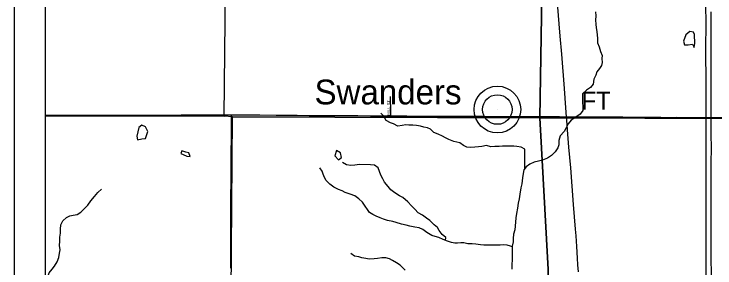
# Model space of a CAD drawing. Extents: x 0 to 1391, y -24 to 440.
# Drawn here: x 490 to 534.79, y 365.71 to 381.91 of the extents above; entities that cross this region are included whole.
import ezdxf

# ---------------------------------------------------------------- set-up
doc = ezdxf.new("R2010")
doc.units = 0
for name, color, linetype in [('GM_X_County_Road', 7, 'Continuous'), ('GM_X_County_Road_Text', 7, 'Continuous'), ('GM_X_Interstate_Route', 7, 'Continuous'), ('GM_X_Minor_Lake', 7, 'Continuous'), ('GM_X_Minor_River', 7, 'Continuous'), ('GM_X_Section', 7, 'Continuous'), ('GM_X_Township', 7, 'Continuous'), ('GM_X_Township_Road', 7, 'Continuous'), ('GM_X_Township_Subdivision', 7, 'Continuous'), ('GM_X_Township_Subdivision_Text', 7, 'Continuous'), ('GM_X_Unincorporated', 7, 'Continuous'), ('GM_X_Unincorporated_Location', 7, 'Continuous'), ('GM_X_Unincorporated_Text', 7, 'Continuous'), ('SH_Data', 7, 'Continuous')]:
    doc.layers.add(name, color=color, linetype=linetype)

msp = doc.modelspace()

# ---------------------------------------------------------------- linework, layer by layer
at = {"layer": 'GM_X_County_Road'}
for points in [[(525.306, 375.36), (525.265, 375.917), (525.169, 377.156), (524.994, 379.348), (524.898, 380.487), (524.731, 382.594), (524.682, 383.226), (524.546, 384.923), (524.496, 385.53), (524.433, 386.31), (524.345, 387.425), (524.25, 388.552), (524.156, 389.753), (524.084, 390.608), (524.005, 391.636), (523.947, 392.283)], [(492, 375.458), (492.953, 375.453), (494.159, 375.455), (495.712, 375.459), (496.11, 375.458), (496.47, 375.458), (497.079, 375.466), (497.899, 375.462), (498.67, 375.462), (499.341, 375.463), (500.086, 375.462), (500.671, 375.471), (501.292, 375.476), (501.677, 375.479), (502.013, 375.479), (503.082, 375.481), (503.84, 375.48), (503.894, 375.481)], [(503.894, 375.481), (504.386, 375.484), (504.809, 375.482), (505.256, 375.477), (505.716, 375.472), (506.747, 375.458), (507.505, 375.452), (508.089, 375.448), (508.86, 375.441), (509.344, 375.439), (509.73, 375.435), (509.991, 375.433), (510.425, 375.43), (511.022, 375.429), (511.382, 375.429), (511.978, 375.426), (512.773, 375.417), (513.158, 375.409), (514.073, 375.406)], [(514.073, 375.406), (514.897, 375.406), (515.092, 375.405)], [(515.092, 375.405), (515.431, 375.403), (515.854, 375.402), (516.587, 375.402), (517.271, 375.402), (517.544, 375.398), (517.705, 375.395), (518.103, 375.396), (518.712, 375.389), (518.823, 375.387), (519.146, 375.384), (519.369, 375.386), (520.014, 375.385), (520.374, 375.382), (520.685, 375.378), (521.231, 375.372), (521.827, 375.371), (523.406, 375.371), (524.388, 375.368), (524.848, 375.365), (525.306, 375.36)], [(526.06, 365.472), (526.036, 365.906), (526.013, 366.34), (525.966, 367.072), (525.916, 367.766), (525.882, 368.187), (525.758, 369.76), (525.569, 372.089), (525.461, 373.426), (525.373, 374.529), (525.323, 375.136), (525.306, 375.36)], [(525.306, 375.36), (525.324, 375.359), (525.581, 375.358), (525.991, 375.357), (526.513, 375.355), (527.172, 375.35), (527.83, 375.347), (528.911, 375.341), (529.707, 375.336), (530.204, 375.331), (530.751, 375.329), (531.024, 375.332), (531.323, 375.324), (531.807, 375.319), (532.353, 375.32), (533.346, 375.317), (533.794, 375.315), (534.218, 375.312), (534.553, 375.312), (535.968, 375.307)]]:
    msp.add_lwpolyline(points, dxfattribs=at)
at = {"layer": 'GM_X_Interstate_Route'}
for points in [[(534.218, 365.027), (534.22, 365.922), (534.222, 366.63), (534.218, 368.333), (534.222, 369.501), (534.218, 370.408), (534.22, 371.601), (534.217, 372.546), (534.217, 374.36), (534.218, 375.312), (534.216, 376.386), (534.218, 377.815), (534.214, 379.282), (534.213, 379.928), (534.216, 381.071), (534.213, 382.737)], [(534.557, 365.164), (534.554, 366.494), (534.551, 367.078), (534.552, 368.768), (534.554, 369.265), (534.555, 369.738), (534.555, 370.086), (534.552, 370.694), (534.552, 371.266), (534.553, 371.962), (534.554, 372.385), (534.555, 372.496), (534.555, 372.77), (534.556, 372.993), (534.556, 373.043), (534.556, 373.242), (534.555, 374.36), (534.553, 375.312), (534.551, 376.808), (534.551, 377.505), (534.55, 378.25), (534.551, 378.511), (534.547, 379.791), (534.545, 380.239), (534.547, 380.674), (534.551, 382.041)]]:
    msp.add_lwpolyline(points, dxfattribs=at)
at = {"layer": 'GM_X_Minor_Lake'}
for p, q in [((500.722, 373.183), (500.652, 373.016)), ((500.652, 373.016), (500.817, 372.946)), ((501.248, 372.832), (501.176, 373.045)), ((510.931, 372.75), (510.868, 373.062))]:
    msp.add_line(p, q, dxfattribs=at)
for points in [[(533.472, 380.598), (533.423, 380.76), (533.18, 380.795), (532.925, 380.581), (532.787, 380.178)], [(532.787, 380.178), (532.846, 379.946), (533.081, 379.949), (533.356, 379.981), (533.451, 379.774), (533.509, 380.038), (533.472, 380.598)], [(498.547, 374.419), (498.4, 374.707), (498.159, 374.81), (497.966, 374.663), (497.844, 374.121)], [(497.844, 374.121), (497.899, 373.884), (498.159, 373.954), (498.402, 373.972), (498.547, 374.419)], [(501.176, 373.045), (500.979, 373.095), (500.722, 373.183)], [(510.868, 373.062), (510.612, 373.211), (510.495, 372.862)], [(500.817, 372.946), (501.051, 372.851), (501.248, 372.832)], [(510.495, 372.862), (510.731, 372.618), (510.931, 372.75)]]:
    msp.add_lwpolyline(points, dxfattribs=at)
at = {"layer": 'GM_X_Minor_River'}
for points in [[(527.162, 382.048), (527.167, 381.798), (527.155, 381.518), (527.167, 381.268), (527.202, 381.017), (527.237, 380.789), (527.257, 380.554), (527.285, 380.364), (527.281, 380.069), (527.392, 379.809), (527.479, 379.528), (527.575, 379.268), (527.557, 379.072), (527.577, 378.821), (527.544, 378.625), (527.42, 378.43), (527.25, 378.221), (527.171, 378.017), (527.038, 377.747), (527.004, 377.444), (526.833, 377.212), (526.58, 377.057), (526.334, 376.818), (526.33, 376.546), (526.319, 376.258), (526.354, 376.015), (526.336, 375.765), (526.18, 375.525), (525.889, 375.34), (525.605, 375.141), (525.412, 374.909), (525.279, 374.653), (525.147, 374.413), (524.907, 374.129), (524.812, 373.842), (524.809, 373.57), (524.738, 373.374), (524.575, 373.111), (524.343, 372.88), (524.09, 372.717), (523.769, 372.594), (523.502, 372.522), (523.235, 372.458), (522.967, 372.334), (522.729, 372.156)], [(522.729, 372.156), (522.644, 372.051), (522.632, 372.309), (522.643, 372.559), (522.649, 373.021), (522.637, 373.279), (522.395, 373.419), (522.122, 373.461), (521.932, 373.472), (521.735, 373.483), (521.453, 373.48), (521.217, 373.476), (520.989, 373.464), (520.73, 373.461), (520.464, 373.435), (520.199, 373.522), (519.901, 373.459), (519.688, 373.432), (519.452, 373.413), (519.185, 373.402), (518.927, 373.414), (518.723, 373.531), (518.489, 373.701), (518.3, 373.735), (518.095, 373.783), (517.777, 373.91), (517.566, 374.011), (517.369, 374.128), (517.097, 374.246), (516.825, 374.356), (516.622, 374.557), (516.418, 374.651), (516.175, 374.693), (515.978, 374.756), (515.712, 374.806), (515.484, 374.81), (515.226, 374.821), (515.028, 374.832), (514.807, 374.79), (514.533, 374.764), (514.245, 374.897), (514.049, 374.961), (513.777, 375.117), (513.62, 375.384), (513.441, 375.592)], [(517.577, 367.473), (517.59, 367.661), (517.357, 367.854), (517.162, 368.1), (517.058, 368.298), (516.847, 368.453), (516.577, 368.746), (516.358, 368.885), (516.095, 369.071), (515.83, 369.219), (515.605, 369.466), (515.403, 369.673), (515.163, 369.935), (514.854, 370.205), (514.635, 370.322), (514.326, 370.509), (514.077, 370.687), (513.913, 370.917), (513.673, 371.186), (513.562, 371.407), (513.428, 371.637), (513.362, 371.857), (513.259, 372.101), (513.04, 372.264), (512.782, 372.298), (512.067, 372.309), (511.785, 372.276), (511.526, 372.257), (511.246, 372.292), (510.981, 372.44)], [(521.828, 367.054), (521.728, 367.095), (521.501, 367.159), (521.25, 367.178), (521.06, 367.174), (520.801, 367.171), (520.611, 367.166), (520.025, 367.175), (519.805, 367.194), (519.501, 367.237), (519.281, 367.255), (519, 367.26), (518.742, 367.317), (518.552, 367.312), (518.346, 367.293), (518.156, 367.296), (517.951, 367.345), (517.693, 367.425), (517.429, 367.535), (517.141, 367.653), (516.914, 367.717), (516.694, 367.774), (516.377, 367.976), (516.129, 368.169), (515.886, 368.264), (515.621, 368.313), (515.287, 368.379), (515.052, 368.444), (514.749, 368.509), (514.423, 368.605), (514.196, 368.669), (513.862, 368.75), (513.612, 368.83), (513.4, 368.909), (513.15, 369.011), (512.931, 369.113), (512.712, 369.253), (512.578, 369.445), (512.444, 369.651), (512.272, 369.904), (512.024, 370.12), (511.775, 370.313), (511.488, 370.416), (511.162, 370.535), (510.965, 370.622), (510.731, 370.724), (510.436, 370.872), (510.172, 371.051), (509.955, 371.289), (509.836, 371.488), (509.747, 371.701), (509.689, 371.892), (509.539, 372.091)], [(522.729, 372.156), (522.582, 371.969), (522.541, 371.727), (522.5, 371.462), (522.441, 371.069), (522.385, 370.828), (522.311, 370.412), (522.269, 370.117), (522.22, 369.853), (522.163, 369.52), (522.105, 369.18), (522.063, 368.908), (522.011, 368.379), (521.993, 368.152), (521.921, 367.865), (521.902, 367.585), (521.884, 367.388), (521.827, 367.109), (521.831, 366.813), (521.82, 366.533), (521.808, 365.646)], [(492.903, 366.667), (492.959, 366.871), (492.909, 367.144), (492.928, 367.424), (492.931, 367.682), (492.965, 367.931), (492.968, 368.181), (492.987, 368.469), (493.12, 368.725), (493.358, 368.94), (493.572, 369.036), (493.771, 369.078), (494.03, 369.112), (494.268, 369.267), (494.476, 369.491), (494.715, 369.722), (494.916, 369.984), (495.132, 370.261), (495.356, 370.523), (495.595, 370.731)], [(492, 364.621), (492.01, 364.636), (492.111, 364.869), (492.153, 365.133), (492.255, 365.412), (492.433, 365.629), (492.588, 365.831), (492.751, 366.109), (492.854, 366.38), (492.903, 366.667)], [(515, 365.58), (514.677, 365.888), (514.443, 366.044), (514.186, 366.199), (513.982, 366.286), (513.747, 366.365), (513.497, 366.369), (513.23, 366.32), (513.009, 366.293), (512.689, 366.283), (512.477, 366.317), (512.234, 366.351), (512.037, 366.415), (511.756, 366.464), (511.515, 366.635)]]:
    msp.add_lwpolyline(points, dxfattribs=at)
at = {"layer": 'GM_X_Section'}
for p, q in [((492, 388.207), (492, 375.413)), ((492, 375.413), (492, 355.562))]:
    msp.add_line(p, q, dxfattribs=at)
for points in [[(530.802, 393.045), (543.962, 394.707), (543.747, 375.22), (523.606, 375.279), (523.87, 392.175)], [(523.87, 392.175), (523.606, 375.279), (503.957, 375.36), (503.435, 375.392), (503.573, 389.632), (510.734, 390.543)], [(503.957, 375.36), (523.606, 375.279), (524.129, 365.618), (524.116, 355.619), (503.806, 355.568)], [(543.747, 375.22), (543.666, 355.101), (524.116, 355.619), (524.129, 365.618), (523.606, 375.279)]]:
    msp.add_lwpolyline(points, close=True, dxfattribs=at)
for points in [[(492, 375.413), (503.435, 375.392), (503.573, 389.632), (492, 388.207)], [(492, 355.562), (503.806, 355.568), (503.957, 375.36), (503.435, 375.392), (492, 375.413)]]:
    msp.add_lwpolyline(points, dxfattribs=at)
at = {"layer": 'GM_X_Township'}
msp.add_lwpolyline([(563.833, 373.178), (563.849, 374.981), (563.918, 383.057), (564.071, 397.264), (576.025, 398.776), (588.961, 400.394), (591.398, 400.66), (591.42, 402.56), (591.526, 412.457), (591.623, 418), (492, 418), (492, 315.227)], dxfattribs=at)
at = {"layer": 'GM_X_Township_Road'}
msp.add_lwpolyline([(503.846, 365.703), (503.852, 367.057), (503.854, 367.728), (503.85, 368.312), (503.854, 368.884), (503.861, 369.542), (503.864, 370.325), (503.869, 371.145), (503.875, 372.673), (503.875, 373.096), (503.887, 373.989), (503.886, 374.71), (503.886, 375.033), (503.892, 375.382), (503.894, 375.481)], dxfattribs=at)
at = {"layer": 'GM_X_Township_Subdivision'}
msp.add_lwpolyline([(514.073, 375.406), (514.069, 375.926), (514.062, 376.385), (514.054, 376.658)], dxfattribs=at)
at = {"layer": 'GM_X_Unincorporated'}
for radius in [1.488, 0.943]:
    msp.add_circle((520.885, 375.818), radius, dxfattribs=at)
at = {"layer": 'GM_X_Unincorporated_Location'}
msp.add_line((520.885, 375.818), (520.885, 375.818), dxfattribs=at)
at = {"layer": 'SH_Data'}
for p, q in [((490, 420), (490, 280)), ((492, 418), (492, 282)), ((492, 418), (492, 282))]:
    msp.add_line(p, q, dxfattribs=at)

# ---------------------------------------------------------------- texts
at = {"layer": 'GM_X_County_Road_Text'}
msp.add_text('FT', height=1.1364, rotation=0, dxfattribs=at).set_placement((526.269, 375.81))
at = {"layer": 'GM_X_Township_Subdivision_Text'}
msp.add_text('MILL ST', height=0.1894, rotation=90, dxfattribs=at).set_placement((514.033, 375.43))
at = {"layer": 'GM_X_Unincorporated_Text'}
msp.add_text('Swanders', height=1.5795, rotation=0, dxfattribs=at).set_placement((509.202, 376.146))

doc.saveas('drawing.dxf')
